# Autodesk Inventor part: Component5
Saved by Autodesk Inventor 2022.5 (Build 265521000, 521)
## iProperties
Created: 2024-12
Part Number: Component5
Material: Generic
Document SubType Name: Modeling
Designer: AdminForWorker
Density: 1 g/cm^3
Appearance: Default
Title: Component5
Author: AdminForWorker
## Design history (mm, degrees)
feature "Body1"
body "Solid1"
